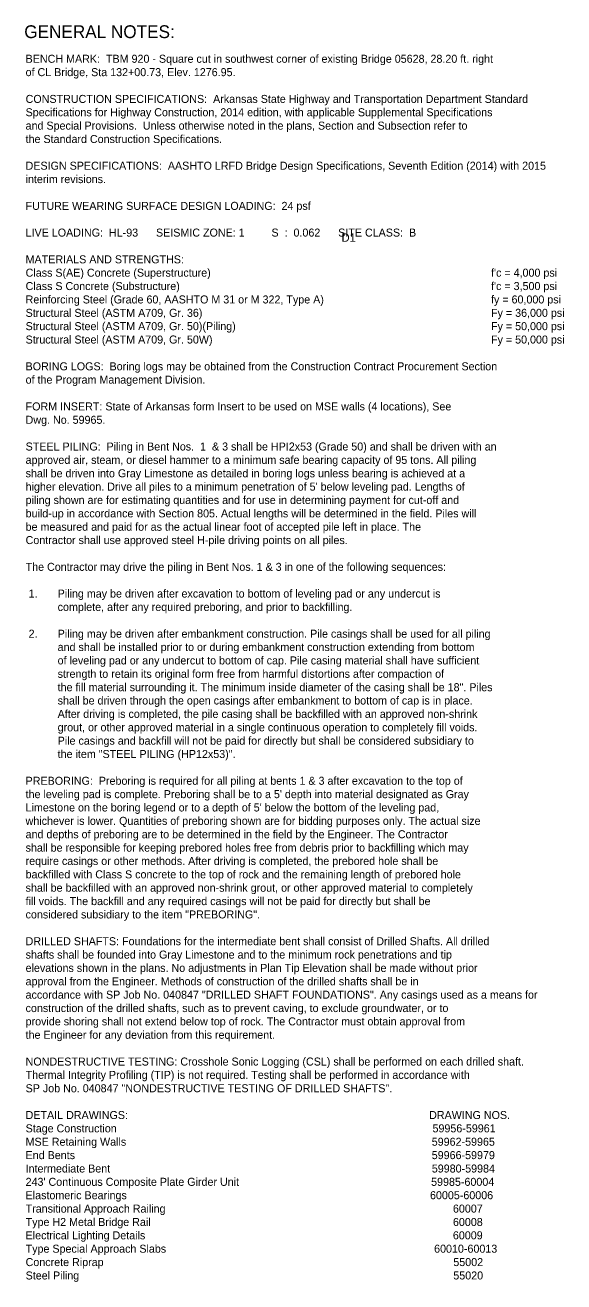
# Model space of a CAD drawing. Extents: x -30246.4 to -30216.9, y 5204.8 to 5224.5.
# Drawn here: x -30246.37 to -30237.97, y 5204.83 to 5224.45 of the extents above; entities that cross this region are included whole.
import ezdxf

# ---------------------------------------------------------------- set-up
doc = ezdxf.new("R2010")
doc.units = 0
doc.layers.add('18', color=7, linetype='Continuous')
doc.layers.add('19', color=7, linetype='Continuous')

msp = doc.modelspace()

# ---------------------------------------------------------------- texts
at = {"layer": '18'}
for s, height, p in [('BENCH MARK:  TBM 920 - Square cut in southwest corner of existing Bridge 05628, 28.20 ft. right ', 0.125, (-30246.364, 5223.867)), ('of CL Bridge, Sta 132+00.73, Elev. 1276.95.', 0.125, (-30246.364, 5223.658)), ('CONSTRUCTION SPECIFICATIONS:  Arkansas State Highway and Transportation Department Standard ', 0.125, (-30246.364, 5223.24)), ('Specifications for Highway Construction, 2014 edition, with applicable Supplemental Specifications ', 0.125, (-30246.364, 5223.032)), ('and Special Provisions.  Unless otherwise noted in the plans, Section and Subsection refer to ', 0.125, (-30246.364, 5222.823)), ('the Standard Construction Specifications.', 0.125, (-30246.364, 5222.614)), ('DESIGN SPECIFICATIONS:  AASHTO LRFD Bridge Design Specifications, Seventh Edition (2014) with 2015 ', 0.125, (-30246.364, 5222.197)), ('interim revisions.', 0.125, (-30246.364, 5221.988)), ('FUTURE WEARING SURFACE DESIGN LOADING:  24 psf', 0.125, (-30246.364, 5221.57)), ('LIVE LOADING:  HL-93      SEISMIC ZONE: 1         S  :  0.062      SITE CLASS:  B', 0.125, (-30246.364, 5221.153)), ('D1', 0.13, (-30241.434, 5221.072)), ('MATERIALS AND STRENGTHS:', 0.125, (-30246.364, 5220.735)), ('Class S(AE) Concrete (Superstructure)', 0.125, (-30246.364, 5220.527)), ("f'c = 4,000 psi", 0.125, (-30239.102, 5220.527)), ('Class S Concrete (Substructure)', 0.125, (-30246.364, 5220.318)), ("f'c = 3,500 psi", 0.125, (-30239.102, 5220.318)), ('Reinforcing Steel (Grade 60, AASHTO M 31 or M 322, Type A)', 0.125, (-30246.364, 5220.109)), ('fy = 60,000 psi', 0.125, (-30239.102, 5220.109)), ('Structural Steel (ASTM A709, Gr. 36)', 0.125, (-30246.364, 5219.9)), ('Fy = 36,000 psi', 0.125, (-30239.102, 5219.9)), ('Structural Steel (ASTM A709, Gr. 50)(Piling)', 0.125, (-30246.364, 5219.692)), ('Fy = 50,000 psi', 0.125, (-30239.102, 5219.692)), ('Structural Steel (ASTM A709, Gr. 50W)', 0.125, (-30246.364, 5219.483)), ('Fy = 50,000 psi', 0.125, (-30239.102, 5219.483)), ('BORING LOGS:  Boring logs may be obtained from the Construction Contract Procurement Section ', 0.125, (-30246.364, 5219.065)), ('of the Program Management Division.', 0.125, (-30246.364, 5218.857)), ('FORM INSERT: State of Arkansas form Insert to be used on MSE walls (4 locations), See', 0.125, (-30246.364, 5218.439)), ('Dwg. No. 59965.', 0.125, (-30246.364, 5218.23)), ('STEEL PILING:  Piling in Bent Nos.  1  & 3 shall be HPI2x53 (Grade 50) and shall be driven with an ', 0.125, (-30246.364, 5217.813)), ('approved air, steam, or diesel hammer to a minimum safe bearing capacity of 95 tons. All piling ', 0.125, (-30246.364, 5217.604)), ('shall be driven into Gray Limestone as detailed in boring logs unless bearing is achieved at a ', 0.125, (-30246.364, 5217.395)), ("higher elevation. Drive all piles to a minimum penetration of 5' below leveling pad. Lengths of ", 0.125, (-30246.364, 5217.187)), ('piling shown are for estimating quantities and for use in determining payment for cut-off and ', 0.125, (-30246.364, 5216.978)), ('build-up in accordance with Section 805. Actual lengths will be determined in the field. Piles will ', 0.125, (-30246.364, 5216.769)), ('be measured and paid for as the actual linear foot of accepted pile left in place. The ', 0.125, (-30246.364, 5216.56)), ('Contractor shall use approved steel H-pile driving points on all piles.', 0.125, (-30246.364, 5216.352)), ('The Contractor may drive the piling in Bent Nos. 1 & 3 in one of the following sequences:', 0.125, (-30246.364, 5215.934)), (' 1.', 0.125, (-30246.364, 5215.517)), ('Piling may be driven after excavation to bottom of leveling pad or any undercut is ', 0.125, (-30245.864, 5215.517)), ('complete, after any required preboring, and prior to backfilling.', 0.125, (-30245.864, 5215.308)), (' 2.', 0.125, (-30246.364, 5214.89)), ('Piling may be driven after embankment construction. Pile casings shall be used for all piling ', 0.125, (-30245.864, 5214.89)), ('and shall be installed prior to or during embankment construction extending from bottom ', 0.125, (-30245.864, 5214.682)), ('of leveling pad or any undercut to bottom of cap. Pile casing material shall have sufficient ', 0.125, (-30245.864, 5214.473)), ('strength to retain its original form free from harmful distortions after compaction of ', 0.125, (-30245.864, 5214.264)), ('the fill material surrounding it. The minimum inside diameter of the casing shall be 18". Piles ', 0.125, (-30245.864, 5214.055)), ('shall be driven through the open casings after embankment to bottom of cap is in place. ', 0.125, (-30245.864, 5213.847)), ('After driving is completed, the pile casing shall be backfilled with an approved non-shrink ', 0.125, (-30245.864, 5213.638)), ('grout, or other approved material in a single continuous operation to completely fill voids. ', 0.125, (-30245.864, 5213.429)), ('Pile casings and backfill will not be paid for directly but shall be considered subsidiary to ', 0.125, (-30245.864, 5213.22)), ('the item "STEEL PILING (HP12x53)".', 0.125, (-30245.864, 5213.012)), ('PREBORING:  Preboring is required for all piling at bents 1 & 3 after excavation to the top of ', 0.125, (-30246.364, 5212.594)), ("the leveling pad is complete. Preboring shall be to a 5' depth into material designated as Gray ", 0.125, (-30246.364, 5212.385)), ("Limestone on the boring legend or to a depth of 5' below the bottom of the leveling pad, ", 0.125, (-30246.364, 5212.177)), ('whichever is lower. Quantities of preboring shown are for bidding purposes only. The actual size ', 0.125, (-30246.364, 5211.968)), ('and depths of preboring are to be determined in the field by the Engineer. The Contractor ', 0.125, (-30246.364, 5211.759)), ('shall be responsible for keeping prebored holes free from debris prior to backfilling which may ', 0.125, (-30246.364, 5211.55)), ('require casings or other methods. After driving is completed, the prebored hole shall be ', 0.125, (-30246.364, 5211.342)), ('backfilled with Class S concrete to the top of rock and the remaining length of prebored hole ', 0.125, (-30246.364, 5211.133)), ('shall be backfilled with an approved non-shrink grout, or other approved material to completely ', 0.125, (-30246.364, 5210.924)), ('fill voids. The backfill and any required casings will not be paid for directly but shall be ', 0.125, (-30246.364, 5210.715)), ('considered subsidiary to the item "PREBORING".', 0.125, (-30246.364, 5210.507)), ('DRILLED SHAFTS: Foundations for the intermediate bent shall consist of Drilled Shafts. All drilled ', 0.125, (-30246.364, 5210.089)), ('shafts shall be founded into Gray Limestone and to the minimum rock penetrations and tip ', 0.125, (-30246.364, 5209.88)), ('elevations shown in the plans. No adjustments in Plan Tip Elevation shall be made without prior ', 0.125, (-30246.364, 5209.672)), ('approval from the Engineer. Methods of construction of the drilled shafts shall be in ', 0.125, (-30246.364, 5209.463)), ('accordance with SP Job No. 040847 "DRILLED SHAFT FOUNDATIONS". Any casings used as a means for ', 0.125, (-30246.364, 5209.254)), ('construction of the drilled shafts, such as to prevent caving, to exclude groundwater, or to ', 0.125, (-30246.364, 5209.045)), ('provide shoring shall not extend below top of rock. The Contractor must obtain approval from ', 0.125, (-30246.364, 5208.837)), ('the Engineer for any deviation from this requirement.', 0.125, (-30246.364, 5208.628)), ('NONDESTRUCTIVE TESTING: Crosshole Sonic Logging (CSL) shall be performed on each drilled shaft. ', 0.125, (-30246.364, 5208.21)), ('Thermal Integrity Profiling (TIP) is not required. Testing shall be performed in accordance with ', 0.125, (-30246.364, 5208.002)), ('SP Job No. 040847 "NONDESTRUCTIVE TESTING OF DRILLED SHAFTS".', 0.125, (-30246.364, 5207.793)), ('DETAIL DRAWINGS:', 0.125, (-30246.364, 5207.375)), ('DRAWING NOS.', 0.125, (-30240.068, 5207.375)), ('Stage Construction', 0.125, (-30246.364, 5207.167)), ('59956-59961', 0.125, (-30240.015, 5207.167)), ('MSE Retaining Walls', 0.125, (-30246.364, 5206.958)), ('59962-59965', 0.125, (-30240.027, 5206.958)), ('End Bents', 0.125, (-30246.364, 5206.749)), ('59966-59979', 0.125, (-30240.027, 5206.749)), ('Intermediate Bent', 0.125, (-30246.364, 5206.54)), ('59980-59984', 0.125, (-30240.026, 5206.54)), ("243' Continuous Composite Plate Girder Unit", 0.125, (-30246.364, 5206.332)), ('59985-60004', 0.125, (-30240.037, 5206.332)), ('Elastomeric Bearings', 0.125, (-30246.364, 5206.123)), ('60005-60006', 0.125, (-30240.054, 5206.123)), ('Transitional Approach Railing', 0.125, (-30246.364, 5205.914)), ('60007', 0.125, (-30239.696, 5205.914)), ('Type H2 Metal Bridge Rail', 0.125, (-30246.364, 5205.705)), ('60008', 0.125, (-30239.696, 5205.705)), ('Electrical Lighting Details', 0.125, (-30246.364, 5205.497)), ('60009', 0.125, (-30239.697, 5205.497)), ('Type Special Approach Slabs', 0.125, (-30246.364, 5205.288)), ('60010-60013', 0.125, (-30239.99, 5205.288)), ('Concrete Riprap', 0.125, (-30246.364, 5205.079)), ('55002', 0.125, (-30239.69, 5205.079)), ('Steel Piling', 0.125, (-30246.364, 5204.87)), ('55020', 0.125, (-30239.69, 5204.87))]:
    msp.add_text(s, height=height, dxfattribs=at).set_placement(p)
at = {"layer": '19'}
msp.add_text('GENERAL NOTES:', height=0.2, dxfattribs=at).set_placement((-30246.385, 5224.252))

doc.saveas('drawing.dxf')
